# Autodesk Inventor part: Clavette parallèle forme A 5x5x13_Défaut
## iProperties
Shininess: 64.0
Length Units: 11269
Angle Units: 11279
Time Units: 11290
Mass Units: 11283
Length Display Precision: 3
Angle Display Precision: 2
Compacted: True
Part Number: Clavette parallèle forme A 5x5x13_Défaut
Document SubType Name: Modeling
Created: 2006-01
Material: Par défaut
Designer: riri
Density: 0.0
Volumn: 0.0
Area: 0.0
PropertySet Name: Model Information
Control State: 0
Master: False
Checked Out: False
Author: riri
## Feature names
1. Base1
